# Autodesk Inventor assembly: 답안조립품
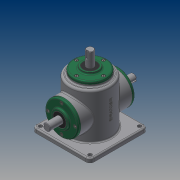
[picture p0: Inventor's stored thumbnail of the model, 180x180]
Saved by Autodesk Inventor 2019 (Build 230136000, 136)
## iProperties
Created: 2019-03
Part Number: 답안조립품
Material: 일반
Document SubType Name: Assembly
Designer: PC312-11
Author: PC312-11
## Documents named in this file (16)
- C:\Users\PC312-11\Desktop\490314V1005\답안조립품.iam
- C:\Users\PC312-11\Desktop\490314V1005\본체.ipt
- C:\Users\PC312-11\Desktop\490314V1005\커버.ipt
- C:\Users\PC312-11\Desktop\490314V1005\오일 실.ipt
- 오일 실.ipt
- C:\Users\PC312-11\Desktop\490314V1005\베어링 6203.ipt
- C:\Users\PC312-11\Desktop\490314V1005\서브 축.ipt
- 서브 축.ipt
- C:\Users\PC312-11\Desktop\490314V1005\메인 축.ipt
- 메인 축.ipt
- C:\Users\PC312-11\Desktop\490314V1005\키 4x4.ipt
- C:\Users\PC312-11\Desktop\490314V1005\키 5x5.ipt
- C:\Users\PC312-11\Desktop\490314V1005\서브 베벨기어.ipt
- C:\Users\PC312-11\Desktop\490314V1005\메인 베벨기어.ipt
- C:\Users\PC312-11\Desktop\490314V1005\볼트 M4.ipt
- 볼트 M4.ipt
